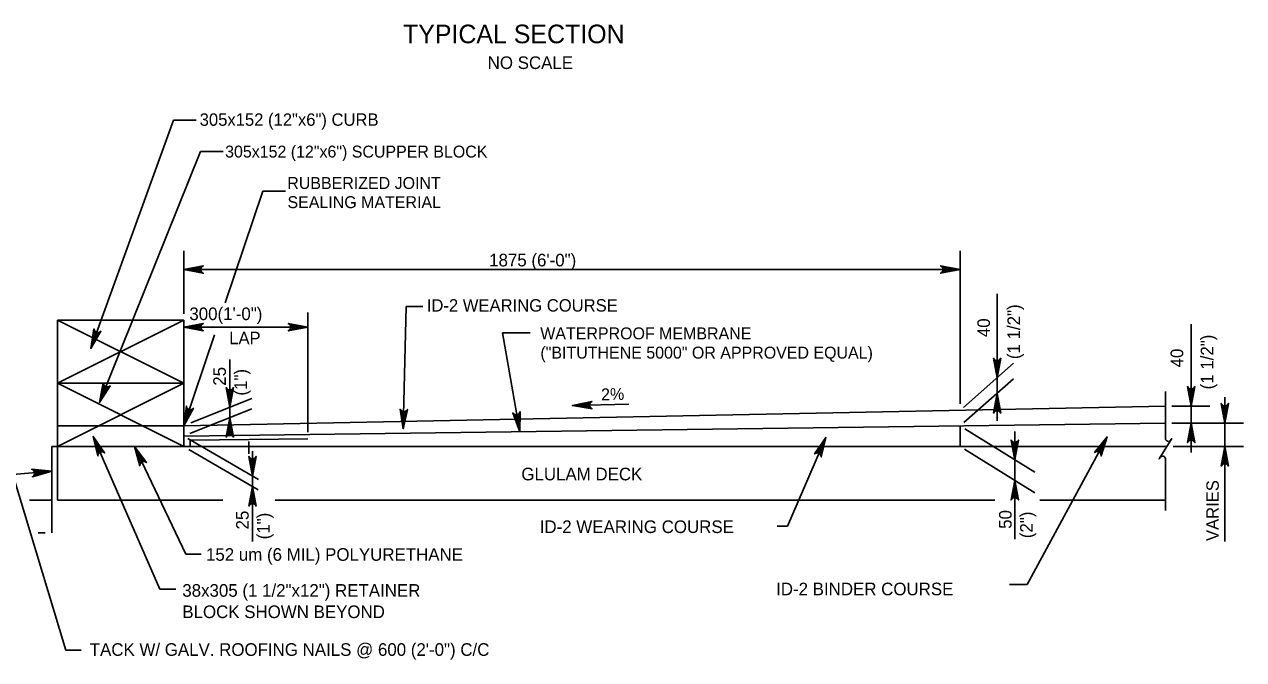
# Model space of a CAD drawing. Extents: x -13 to 81, y -176 to 0.
# Drawn here: x 3.18 to 14.77, y -78.93 to -72.89 of the extents above; entities that cross this region are included whole.
import ezdxf

# ---------------------------------------------------------------- set-up
doc = ezdxf.new("R2010")
doc.units = 0
for name, color, linetype in [('Level 2', 7, 'Continuous'), ('Level 3', 7, 'Continuous'), ('Level 4', 7, 'Continuous'), ('Level 52', 7, 'Continuous')]:
    doc.layers.add(name, color=color, linetype=linetype)

msp = doc.modelspace()

# ---------------------------------------------------------------- linework, layer by layer
at = {"layer": 'Level 2'}
for p, q in [((4.597, -73.798), (4.811, -73.798)), ((4.854, -74.096), (5.068, -74.096)), ((5.447, -74.472), (5.661, -74.472)), ((4.693, -75.638), (4.693, -75.041)), ((12.075, -76.495), (12.075, -75.041)), ((4.693, -75.218), (12.075, -75.218)), ((12.425, -76.129), (12.425, -75.449)), ((5.874, -76.766), (5.874, -75.627)), ((6.808, -75.57), (6.965, -75.57)), ((4.693, -75.765), (5.874, -75.765)), ((14.271, -76.399), (14.271, -75.739)), ((7.725, -75.819), (7.986, -75.819)), ((5.132, -76.414), (5.132, -76.074)), ((12.106, -76.529), (12.583, -76.11)), ((12.11, -76.673), (12.582, -76.258)), ((12.425, -76.395), (12.425, -76.247)), ((14.026, -76.377), (14.026, -76.824)), ((4.76, -76.677), (5.34, -76.444)), ((14.592, -76.56), (14.592, -76.432)), ((4.753, -76.778), (5.34, -76.542)), ((5.132, -76.63), (5.132, -76.532)), ((8.388, -76.512), (8.924, -76.498)), ((12.425, -76.513), (12.425, -76.658)), ((14.088, -76.517), (14.448, -76.517)), ((14.271, -76.678), (14.271, -76.517)), ((14.088, -76.678), (14.769, -76.678)), ((14.088, -76.678), (14.448, -76.678)), ((14.592, -76.678), (14.592, -76.901)), ((4.732, -76.825), (5.404, -77.215)), ((12.12, -76.732), (12.784, -77.145)), ((12.593, -76.912), (12.593, -76.757)), ((14.271, -76.796), (14.271, -76.957)), ((4.742, -76.929), (5.402, -77.312)), ((5.311, -76.852), (5.311, -76.971)), ((5.348, -77.064), (5.348, -76.946)), ((12.117, -76.927), (12.784, -77.342)), ((14.101, -76.901), (14.769, -76.901)), ((12.593, -77.03), (12.593, -77.227)), ((14.026, -77.018), (14.026, -77.51)), ((14.592, -77.019), (14.592, -77.806)), ((5.348, -77.182), (5.348, -77.281)), ((3.43, -77.412), (3.228, -77.412)), ((5.348, -77.399), (5.348, -77.803)), ((12.593, -77.345), (12.593, -77.781)), ((3.377, -77.721), (3.309, -77.721)), ((10.335, -77.658), (10.432, -77.658)), ((4.713, -77.924), (4.859, -77.924)), ((12.542, -78.214), (12.711, -78.214)), ((4.466, -78.257), (4.618, -78.257))]:
    msp.add_line(p, q, dxfattribs=at)
for points in [[(3.809, -75.969), (4.597, -73.798)], [(3.892, -76.482), (4.854, -74.096)], [(5.088, -75.534), (5.447, -74.472)], [(6.78, -76.733), (6.808, -75.57)], [(4.693, -76.704), (4.985, -75.838)], [(7.888, -76.76), (7.725, -75.819)], [(3.834, -76.805), (4.466, -78.257)], [(10.796, -76.815), (10.432, -77.658)], [(13.472, -76.81), (12.711, -78.214)], [(14.079, -76.838), (14.086, -76.826), (13.965, -77.019), (13.974, -77.006)], [(4.226, -76.901), (4.713, -77.924)], [(3.438, -77.137), (3.07, -77.168)]]:
    msp.add_lwpolyline(points, dxfattribs=at)
for points in [[(4.811, -75.198), (4.811, -75.237), (4.693, -75.218)], [(11.956, -75.198), (11.956, -75.237), (12.075, -75.218)], [(4.811, -75.745), (4.811, -75.784), (4.693, -75.765)], [(5.756, -75.745), (5.756, -75.784), (5.874, -75.765)], [(3.809, -75.969), (3.812, -75.965), (3.81, -75.964)], [(12.405, -76.129), (12.445, -76.129), (12.425, -76.247)], [(3.892, -76.482), (3.895, -76.478), (3.893, -76.478)], [(5.112, -76.414), (5.151, -76.414), (5.132, -76.532)], [(8.502, -76.528), (8.501, -76.49), (8.388, -76.512)], [(12.405, -76.513), (12.445, -76.513), (12.425, -76.395)], [(14.251, -76.399), (14.291, -76.399), (14.271, -76.517)], [(14.572, -76.56), (14.612, -76.56), (14.592, -76.678)], [(4.693, -76.704), (4.695, -76.7), (4.693, -76.699)], [(5.112, -76.748), (5.151, -76.748), (5.132, -76.63)], [(6.78, -76.733), (6.782, -76.728), (6.779, -76.728)], [(7.888, -76.76), (7.878, -76.642), (7.858, -76.645)], [(14.251, -76.796), (14.291, -76.796), (14.271, -76.678)], [(3.834, -76.805), (3.835, -76.81), (3.837, -76.809)], [(10.796, -76.815), (10.793, -76.819), (10.795, -76.82)], [(13.472, -76.81), (13.468, -76.814), (13.471, -76.815)], [(4.34, -76.901), (4.341, -76.905), (4.343, -76.904)], [(12.573, -76.912), (12.613, -76.912), (12.593, -77.03)], [(14.572, -77.019), (14.612, -77.019), (14.592, -76.901)], [(5.328, -77.064), (5.367, -77.064), (5.348, -77.182)], [(3.438, -77.137), (3.433, -77.136), (3.433, -77.138)], [(5.328, -77.399), (5.367, -77.399), (5.348, -77.281)], [(12.573, -77.345), (12.613, -77.345), (12.593, -77.227)]]:
    msp.add_lwpolyline(points, close=True, dxfattribs=at)
for centre, start, end in [((14.054, -76.824), 180, 330), ((13.998, -77.021), 5.3286, 147.8672)]:
    msp.add_arc(centre, 0.0284, start, end, dxfattribs=at)
at = {"layer": 'Level 3'}
for p, q in [((3.492, -75.7), (3.492, -77.412)), ((3.492, -75.7), (4.693, -75.7)), ((3.492, -75.7), (4.693, -76.3)), ((3.492, -76.3), (4.693, -75.7)), ((4.693, -75.7), (4.693, -76.901)), ((4.693, -76.3), (3.492, -76.3)), ((4.693, -76.3), (3.492, -76.901)), ((3.492, -76.3), (4.693, -76.901)), ((4.693, -76.704), (14.026, -76.517)), ((4.693, -76.704), (3.492, -76.704)), ((4.693, -76.802), (14.026, -76.678)), ((12.075, -76.704), (12.075, -76.901)), ((4.754, -76.842), (5.874, -76.827)), ((4.754, -76.842), (4.754, -76.901)), ((3.438, -76.901), (3.438, -77.721)), ((3.438, -76.901), (4.754, -76.901)), ((4.754, -76.901), (14.04, -76.901)), ((3.492, -77.412), (5.066, -77.412)), ((5.562, -77.412), (12.404, -77.412)), ((12.832, -77.412), (14.026, -77.412))]:
    msp.add_line(p, q, dxfattribs=at)
at = {"layer": 'Level 4'}
msp.add_lwpolyline([(3.718, -78.838), (3.573, -78.838), (3.07, -77.168)], dxfattribs=at)
at = {"layer": 'Level 52'}
for points in [[(4.693, -75.218), (4.879, -75.183), (4.865, -75.193), (4.857, -75.205), (4.855, -75.218), (4.857, -75.23), (4.865, -75.243), (4.879, -75.253), (4.693, -75.218), (4.865, -75.243), (4.857, -75.23), (4.693, -75.218), (4.855, -75.218), (4.857, -75.205), (4.693, -75.218), (4.865, -75.193)], [(12.075, -75.218), (11.888, -75.253), (11.902, -75.243), (11.91, -75.23), (11.912, -75.218), (11.91, -75.205), (11.902, -75.193), (11.888, -75.183), (12.075, -75.218), (11.902, -75.193), (11.91, -75.205), (12.075, -75.218), (11.912, -75.218), (11.91, -75.23), (12.075, -75.218), (11.902, -75.243)], [(3.809, -75.969), (3.84, -75.782), (3.844, -75.799), (3.854, -75.81), (3.865, -75.816), (3.877, -75.818), (3.891, -75.816), (3.906, -75.805), (3.809, -75.969), (3.891, -75.816), (3.877, -75.818), (3.809, -75.969), (3.865, -75.816), (3.854, -75.81), (3.809, -75.969), (3.844, -75.799)], [(4.693, -75.765), (4.879, -75.73), (4.865, -75.74), (4.857, -75.752), (4.855, -75.765), (4.857, -75.777), (4.865, -75.79), (4.879, -75.8), (4.693, -75.765), (4.865, -75.79), (4.857, -75.777), (4.693, -75.765), (4.855, -75.765), (4.857, -75.752), (4.693, -75.765), (4.865, -75.74)], [(5.874, -75.765), (5.687, -75.8), (5.702, -75.79), (5.709, -75.777), (5.711, -75.765), (5.709, -75.752), (5.702, -75.74), (5.687, -75.73), (5.874, -75.765), (5.702, -75.74), (5.709, -75.752), (5.874, -75.765), (5.711, -75.765), (5.709, -75.777), (5.874, -75.765), (5.702, -75.79)], [(12.425, -76.249), (12.39, -76.062), (12.4, -76.077), (12.413, -76.084), (12.425, -76.086), (12.438, -76.084), (12.45, -76.077), (12.46, -76.062), (12.425, -76.249), (12.45, -76.077), (12.438, -76.084), (12.425, -76.249), (12.425, -76.086), (12.413, -76.084), (12.425, -76.249), (12.4, -76.077)], [(3.892, -76.482), (3.929, -76.296), (3.933, -76.313), (3.942, -76.325), (3.953, -76.332), (3.965, -76.334), (3.98, -76.332), (3.994, -76.323), (3.892, -76.482), (3.98, -76.332), (3.965, -76.334), (3.892, -76.482), (3.953, -76.332), (3.942, -76.325), (3.892, -76.482), (3.933, -76.313)], [(5.132, -76.528), (5.097, -76.341), (5.107, -76.355), (5.119, -76.363), (5.132, -76.365), (5.144, -76.363), (5.157, -76.355), (5.167, -76.341), (5.132, -76.528), (5.157, -76.355), (5.144, -76.363), (5.132, -76.528), (5.132, -76.365), (5.119, -76.363), (5.132, -76.528), (5.107, -76.355)], [(14.271, -76.517), (14.236, -76.331), (14.246, -76.345), (14.259, -76.352), (14.271, -76.355), (14.284, -76.352), (14.296, -76.345), (14.306, -76.331), (14.271, -76.517), (14.296, -76.345), (14.284, -76.352), (14.271, -76.517), (14.271, -76.355), (14.259, -76.352), (14.271, -76.517), (14.246, -76.345)], [(8.388, -76.512), (8.574, -76.472), (8.56, -76.483), (8.553, -76.495), (8.551, -76.508), (8.553, -76.52), (8.561, -76.533), (8.575, -76.542), (8.388, -76.512), (8.561, -76.533), (8.553, -76.52), (8.388, -76.512), (8.551, -76.508), (8.553, -76.495), (8.388, -76.512), (8.56, -76.483)], [(12.425, -76.396), (12.46, -76.583), (12.45, -76.568), (12.438, -76.561), (12.425, -76.559), (12.413, -76.561), (12.4, -76.568), (12.39, -76.583), (12.425, -76.396), (12.4, -76.568), (12.413, -76.561), (12.425, -76.396), (12.425, -76.559), (12.438, -76.561), (12.425, -76.396), (12.45, -76.568)], [(14.592, -76.678), (14.557, -76.491), (14.567, -76.506), (14.579, -76.513), (14.592, -76.515), (14.604, -76.513), (14.617, -76.506), (14.627, -76.491), (14.592, -76.678), (14.617, -76.506), (14.604, -76.513), (14.592, -76.678), (14.592, -76.515), (14.579, -76.513), (14.592, -76.678), (14.567, -76.506)], [(4.693, -76.704), (4.719, -76.516), (4.724, -76.533), (4.734, -76.544), (4.745, -76.55), (4.757, -76.552), (4.771, -76.549), (4.785, -76.538), (4.693, -76.704), (4.771, -76.549), (4.757, -76.552), (4.693, -76.704), (4.745, -76.55), (4.734, -76.544), (4.693, -76.704), (4.724, -76.533)], [(6.78, -76.733), (6.75, -76.546), (6.76, -76.56), (6.772, -76.568), (6.784, -76.571), (6.797, -76.569), (6.809, -76.562), (6.82, -76.548), (6.78, -76.733), (6.809, -76.562), (6.797, -76.569), (6.78, -76.733), (6.784, -76.571), (6.772, -76.568), (6.78, -76.733), (6.76, -76.56)], [(7.888, -76.76), (7.822, -76.582), (7.834, -76.594), (7.848, -76.599), (7.86, -76.599), (7.872, -76.595), (7.883, -76.586), (7.891, -76.57), (7.888, -76.76), (7.883, -76.586), (7.872, -76.595), (7.888, -76.76), (7.86, -76.599), (7.848, -76.599), (7.888, -76.76), (7.834, -76.594)], [(5.132, -76.626), (5.167, -76.812), (5.157, -76.798), (5.144, -76.791), (5.132, -76.788), (5.119, -76.791), (5.107, -76.798), (5.097, -76.812), (5.132, -76.626), (5.107, -76.798), (5.119, -76.791), (5.132, -76.626), (5.132, -76.788), (5.144, -76.791), (5.132, -76.626), (5.157, -76.798)], [(14.271, -76.678), (14.306, -76.864), (14.296, -76.85), (14.284, -76.842), (14.271, -76.84), (14.259, -76.842), (14.246, -76.85), (14.236, -76.864), (14.271, -76.678), (14.246, -76.85), (14.259, -76.842), (14.271, -76.678), (14.271, -76.84), (14.284, -76.842), (14.271, -76.678), (14.296, -76.85)], [(3.834, -76.805), (3.941, -76.962), (3.926, -76.953), (3.911, -76.951), (3.899, -76.954), (3.889, -76.961), (3.88, -76.973), (3.877, -76.99), (3.834, -76.805), (3.88, -76.973), (3.889, -76.961), (3.834, -76.805), (3.899, -76.954), (3.911, -76.951), (3.834, -76.805), (3.926, -76.953)], [(10.796, -76.815), (10.754, -77), (10.751, -76.983), (10.742, -76.971), (10.732, -76.964), (10.72, -76.961), (10.705, -76.963), (10.69, -76.972), (10.796, -76.815), (10.705, -76.963), (10.72, -76.961), (10.796, -76.815), (10.732, -76.964), (10.742, -76.971), (10.796, -76.815), (10.751, -76.983)], [(12.593, -77.026), (12.558, -76.84), (12.568, -76.854), (12.58, -76.861), (12.593, -76.864), (12.605, -76.861), (12.618, -76.854), (12.628, -76.84), (12.593, -77.026), (12.618, -76.854), (12.605, -76.861), (12.593, -77.026), (12.593, -76.864), (12.58, -76.861), (12.593, -77.026), (12.568, -76.854)], [(13.472, -76.81), (13.414, -76.991), (13.412, -76.973), (13.404, -76.961), (13.394, -76.953), (13.382, -76.949), (13.368, -76.949), (13.352, -76.957), (13.472, -76.81), (13.368, -76.949), (13.382, -76.949), (13.472, -76.81), (13.394, -76.953), (13.404, -76.961), (13.472, -76.81), (13.412, -76.973)], [(4.226, -76.901), (4.338, -77.054), (4.323, -77.045), (4.308, -77.044), (4.296, -77.047), (4.286, -77.055), (4.278, -77.067), (4.275, -77.084), (4.226, -76.901), (4.278, -77.067), (4.286, -77.055), (4.226, -76.901), (4.296, -77.047), (4.308, -77.044), (4.226, -76.901), (4.323, -77.045)], [(14.592, -76.901), (14.627, -77.087), (14.617, -77.073), (14.604, -77.065), (14.592, -77.063), (14.579, -77.065), (14.567, -77.073), (14.557, -77.087), (14.592, -76.901), (14.567, -77.073), (14.579, -77.065), (14.592, -76.901), (14.592, -77.063), (14.604, -77.065), (14.592, -76.901), (14.617, -77.073)], [(5.348, -77.182), (5.313, -76.996), (5.323, -77.01), (5.335, -77.018), (5.348, -77.02), (5.36, -77.018), (5.373, -77.01), (5.382, -76.996), (5.348, -77.182), (5.373, -77.01), (5.36, -77.018), (5.348, -77.182), (5.348, -77.02), (5.335, -77.018), (5.348, -77.182), (5.323, -77.01)], [(3.438, -77.137), (3.255, -77.188), (3.268, -77.176), (3.275, -77.163), (3.276, -77.151), (3.272, -77.138), (3.264, -77.126), (3.249, -77.118), (3.438, -77.137), (3.264, -77.126), (3.272, -77.138), (3.438, -77.137), (3.276, -77.151), (3.275, -77.163), (3.438, -77.137), (3.268, -77.176)], [(5.348, -77.281), (5.382, -77.468), (5.373, -77.453), (5.36, -77.446), (5.348, -77.444), (5.335, -77.446), (5.323, -77.453), (5.313, -77.468), (5.348, -77.281), (5.323, -77.453), (5.335, -77.446), (5.348, -77.281), (5.348, -77.444), (5.36, -77.446), (5.348, -77.281), (5.373, -77.453)], [(12.593, -77.223), (12.628, -77.409), (12.618, -77.395), (12.605, -77.388), (12.593, -77.385), (12.58, -77.388), (12.568, -77.395), (12.558, -77.409), (12.593, -77.223), (12.568, -77.395), (12.58, -77.388), (12.593, -77.223), (12.593, -77.385), (12.605, -77.388), (12.593, -77.223), (12.618, -77.395)]]:
    msp.add_lwpolyline(points, dxfattribs=at)

# ---------------------------------------------------------------- texts
at = {"layer": 'Level 2'}
for s, height, p in [('TYPICAL SECTION', 0.17717, (6.778, -73.066)), ('NO SCALE', 0.12, (7.583, -73.311)), ('305x152 (12"x6") CURB', 0.11808, (4.845, -73.851)), ('305x152 (12"x6") SCUPPER BLOCK', 0.11342, (5.087, -74.153)), ('RUBBERIZED JOINT', 0.1135, (5.678, -74.452)), ('SEALING MATERIAL', 0.1135, (5.68, -74.634)), ('ID-2 WEARING COURSE', 0.11808, (7.004, -75.618)), ('WATERPROOF MEMBRANE', 0.1135, (8.083, -75.882)), ('LAP', 0.1181, (5.126, -75.928)), ('("BITUTHENE 5000" OR APPROVED EQUAL)', 0.1135, (8.084, -76.065)), ('GLULAM DECK', 0.12, (7.903, -77.223)), ('ID-2 WEARING COURSE', 0.12, (8.078, -77.724)), ('ID-2 BINDER COURSE', 0.12, (10.325, -78.316))]:
    msp.add_text(s, height=height, dxfattribs=at).set_placement(p)
for s, height, rotation, p in [('2%', 0.1134, 1.5039, (8.663, -76.463)), ('VARIES', 0.1181, 90, (14.533, -77.8))]:
    msp.add_text(s, height=height, rotation=rotation, dxfattribs=at).set_placement(p)
at = {"layer": 'Level 4'}
for s, p in [('1875 (6\'-0")', (7.597, -75.188)), ('300(1\'-0")', (4.747, -75.699)), ('152 um (6 MIL) POLYURETHANE', (4.905, -77.988)), ('38x305 (1 1/2"x12") RETAINER', (4.68, -78.33)), ('BLOCK SHOWN BEYOND', (4.68, -78.533)), ('TACK W/ GALV. ROOFING NAILS @ 600 (2\'-0") C/C', (3.8, -78.892))]:
    msp.add_text(s, height=0.12, dxfattribs=at).set_placement(p)
for s, p in [('(1 1/2")', (12.644, -76.07)), ('40', (12.358, -75.861)), ('(1 1/2")', (14.482, -76.358)), ('40', (14.195, -76.149)), ('25', (5.094, -76.323)), ('(1")', (5.294, -76.417)), ('25', (5.311, -77.69)), ('50', (12.564, -77.684)), ('(2")', (12.764, -77.773)), ('(1")', (5.511, -77.784))]:
    msp.add_text(s, height=0.12, rotation=90, dxfattribs=at).set_placement(p)

doc.saveas('drawing.dxf')
